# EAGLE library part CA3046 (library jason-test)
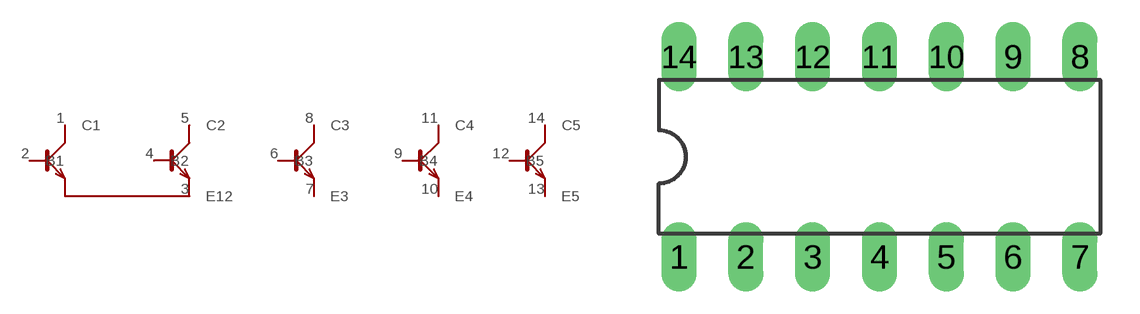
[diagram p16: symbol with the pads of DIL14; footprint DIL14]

Designator prefix -

## CA3046DIL  [DIL14]
1  C1
2  B1
3  E12
4  B2
5  C2
6  B3
7  E3
8  C3
9  B4
10  E4
11  C4
12  B5
13  E5
14  C5

## Footprint DIL14 (pad centres in mm)
Dual In Line Package
drill 0.813 long: 1 -7.62,-3.81; 2 -5.08,-3.81; 3 -2.54,-3.81; 4 0,-3.81; 5 2.54,-3.81; 6 5.08,-3.81; 7 7.62,-3.81; 8 7.62,3.81; 9 5.08,3.81; 10 2.54,3.81; 11 0,3.81; 12 -2.54,3.81; 13 -5.08,3.81; 14 -7.62,3.81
